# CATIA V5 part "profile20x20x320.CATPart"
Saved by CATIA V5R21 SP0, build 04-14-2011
Part number: profile 20x20x320
Bounding box of the stored display mesh (mm): x -24.289 to -4.289, y -1.335 to 18.665, z 0 to 320
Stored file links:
  C:\Users\2027.DESARCY-LEMIE30\Desktop\V16(05.04.2023)\profile20x20x320.CATPart
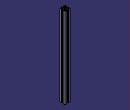
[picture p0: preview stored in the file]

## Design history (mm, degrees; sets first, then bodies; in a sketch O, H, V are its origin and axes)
Body1 (main body)
  Sketch1 on xy-plane, origin (0, 0, 0), H (1, 0, 0), V (0, 1, 0)
    point P1 (-17.2892, 11.6647)
    line L1 (-16.2892, 11.6647) -> (-12.2892, 11.6647)
    point P2 (-11.2892, 11.6647)
    line L2 (-11.2892, 10.6647) -> (-11.2892, 6.6647)
    point P3 (-11.2892, 5.6647)
    line L3 (-12.2892, 5.6647) -> (-16.2892, 5.6647)
    point P4 (-17.2892, 5.6647)
    line L4 (-17.2892, 6.6647) -> (-17.2892, 10.6647)
    point P5 (-24.2892, 18.6647)
    point P6 (-4.2892, 18.6647)
    point P7 (-4.2892, -1.3353)
    line L5 (-11.1892, 18.6647) -> (-11.1892, 16.6647)
    point P8 (-11.1892, 18.6647)
    point P10 (-11.1892, 18.6647)
    point P11 (-17.3892, 18.6647)
    line L6 (-17.3892, 18.6647) -> (-17.3892, 16.6647)
    point P12 (-17.3892, 18.6647)
    line L7 (-11.1892, 18.6647) -> (-4.2892, 18.6647)
    point P14 (-11.1892, 18.6647)
    point P15 (-4.2892, 18.6647)
    point P16 (-11.1892, -1.3353)
    point P17 (-17.3892, -1.3353)
    line L8 (-17.3892, -1.3353) -> (-17.3892, 0.6647)
    point P18 (-17.3892, -1.3353)
    line L9 (-11.1892, -1.3353) -> (-11.1892, 0.6647)
    point P20 (-11.1892, -1.3353)
    line L10 (-24.2892, -1.3353) -> (-17.3892, -1.3353)
    point P22 (-24.2892, -1.3353)
    point P23 (-17.3892, -1.3353)
    line L11 (-11.1892, -1.3353) -> (-4.2892, -1.3353)
    point P24 (-11.1892, -1.3353)
    point P25 (-4.2892, -1.3353)
    line L12 (-24.2892, 18.6647) -> (-17.3892, 18.6647)
    point P26 (-24.2892, 18.6647)
    point P27 (-17.3892, 18.6647)
    point P28 (-4.2892, 5.5647)
    point P29 (-4.2892, 11.7647)
    line L13 (-6.2892, 11.7647) -> (-4.2892, 11.7647)
    point P31 (-4.2892, 11.7647)
    line L14 (-4.2892, 5.5647) -> (-6.2892, 5.5647)
    point P32 (-4.2892, 5.5647)
    point P34 (-24.2892, 5.5647)
    point P35 (-24.2892, 11.7647)
    line L15 (-24.2892, 11.7647) -> (-22.2892, 11.7647)
    point P36 (-24.2892, 11.7647)
    line L16 (-24.2892, 5.5647) -> (-22.2892, 5.5647)
    point P38 (-24.2892, 5.5647)
    line L17 (-4.2892, 18.6647) -> (-4.2892, 11.7647)
    point P40 (-4.2892, 18.6647)
    point P41 (-4.2892, 11.7647)
    line L18 (-24.2892, 18.6647) -> (-24.2892, 11.7647)
    point P42 (-24.2892, 18.6647)
    point P43 (-24.2892, 11.7647)
    line L19 (-24.2892, -1.3353) -> (-24.2892, 5.5647)
    point P44 (-24.2892, -1.3353)
    point P45 (-24.2892, 5.5647)
    line L20 (-4.2892, -1.3353) -> (-4.2892, 5.5647)
    point P46 (-4.2892, -1.3353)
    point P47 (-4.2892, 5.5647)
    line L21 (-22.2892, 5.5647) -> (-22.2892, 1.6647)
    line L22 (-21.2892, 0.6647) -> (-17.3892, 0.6647)
    line L23 (-6.2892, 5.5647) -> (-6.2892, 1.6647)
    line L24 (-11.1892, 0.6647) -> (-7.2892, 0.6647)
    line L25 (-11.1892, 16.6647) -> (-7.2892, 16.6647)
    line L26 (-6.2892, 15.6647) -> (-6.2892, 11.7647)
    line L27 (-17.3892, 16.6647) -> (-21.2892, 16.6647)
    line L28 (-22.2892, 15.6647) -> (-22.2892, 11.7647)
    point P48 (-16.2892, 11.6647)
    point P49 (-17.2892, 10.6647)
    point P50 (-17.2892, 6.6647)
    point P52 (-11.2892, 6.6647)
    point P53 (-11.2892, 10.6647)
    point P54 (-12.2892, 11.6647)
    point P55 (-12.2892, 5.6647)
    line L29 (-16.2892, 11.6647) -> (-21.2892, 16.6647)
    line L30 (-17.2892, 10.6647) -> (-22.2892, 15.6647)
    line L31 (-12.2892, 11.6647) -> (-7.2892, 16.6647)
    line L32 (-16.2892, 5.6647) -> (-21.2892, 0.6647)
    line L33 (-17.2892, 6.6647) -> (-22.2892, 1.6647)
    line L34 (-12.2892, 5.6647) -> (-7.2892, 0.6647)
    line L35 (-11.2892, 6.6647) -> (-6.2892, 1.6647)
    line L36 (-11.2892, 10.6647) -> (-6.2892, 15.6647)
    length L5 = 2
    distance P10 P6 = 6.9
    length L6 = 2
    length L8 = 2
    length L9 = 2
    distance P7 P28 = 6.9
    distance P6 P29 = 6.9
    length L13 = 2
    length L14 = 2
    length L15 = 2
    distance P5 P42 = 0
    length L11 = 6.9
    distance P46 P7 = 0
    distance P1 P48 = 1
    distance P49 P1 = 1
    distance P4 P50 = 1
    distance P54 P2 = 1
    distance P2 P3 = 6
    distance P1 P2 = 6
    horizontal: L1 H, L3 H, L7 H, L10 H, L11 H, L12 H, L13 H, L14 H, L15 H, L16 H, L22 H, L24 H, L25 H, L27 H
    vertical: L2 V, L4 V, L5 V, L6 V, L8 V, L9 V, L17 V, L18 V, L19 V, L20 V, L21 V, L23 V, L26 V, L28 V
    coincidence: P10 P8, P11 P12, P6 P15, P8 P14, P16 L5, P17 L6, P17 P18, P16 P20, P23 L8, P24 L9, P20 P24, P27 L6, P5 P26, P29 P31, P28 P32, P34 L14, P35 L13, P34 P38, P35 P36, P40 L7, P41 L13, P6 P40, P42 L7, P43 L13, P44 L11, P45 L14, P38 P45, P46 L11, P47 L14, P49 L4, P50 L4, P52 L2, P53 L2, P55 L3, P22 P44, P25 P46
    fix: P34, P12, P5, P36, P55
  Pad1: profile Sketch1, direction (0, 0, 1), length 320
  Sketch2 on end face of Pad1, origin (0, 0, 320), H (1, 0, 0), V (0, 1, 0)
    circle A1 centre (-14.2892, 8.6647) radius 2.5
    point P1 (-14.2892, 8.6647)
    reference projected line E1 (-12.2892, 11.6647) -> (-16.2892, 11.6647) from edge [face of Pad1 from Sketch1.L1 | end face of Pad1]
    reference projected line E2 (-11.2892, 6.6647) -> (-11.2892, 10.6647) from edge [face of Pad1 from Sketch1.L2 | end face of Pad1]
    radius A1 = 2.5
    distance P1 E1 = 3
    distance P1 E2 = 3
  Pocket1: profile Sketch2, direction (0, 0, -1), length 320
